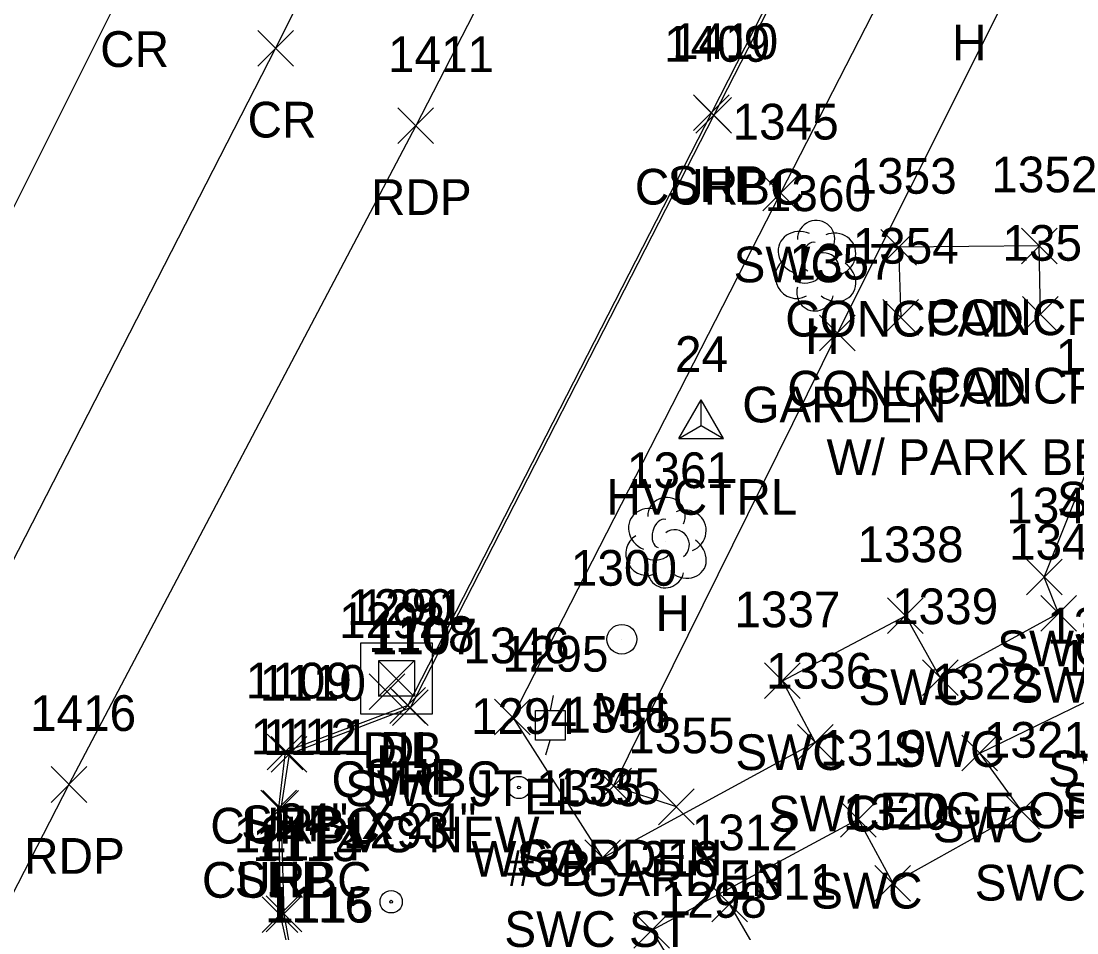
# Model space of a CAD drawing. Extents: x 1462668 to 1465147, y 550359 to 557351.
# Drawn here: x 1464628.9 to 1464688, y 552499.8 to 552550.9 of the extents above; entities that cross this region are included whole.
import ezdxf

# ---------------------------------------------------------------- set-up
doc = ezdxf.new("R2010")
doc.units = 0
for name, color, linetype in [('C_A', 7, 'Continuous'), ('C_I', 7, 'Continuous'), ('CPSM', 7, 'Continuous'), ('D_A', 7, 'Continuous'), ('D_C', 7, 'Continuous'), ('D_I', 7, 'Continuous'), ('D_TIC', 7, 'Continuous'), ('DS', 7, 'Continuous'), ('L_A', 7, 'Continuous'), ('L_C', 7, 'Continuous'), ('L_I', 7, 'Continuous'), ('L_TIC', 7, 'Continuous'), ('LAPB', 7, 'Continuous'), ('LS', 7, 'Continuous'), ('LTD', 7, 'Continuous'), ('P_A', 7, 'Continuous'), ('P_I', 7, 'Continuous'), ('P_TIC', 7, 'Continuous'), ('PET', 7, 'Continuous'), ('PRC', 7, 'Continuous'), ('PSP', 7, 'Continuous'), ('R_A', 7, 'Continuous'), ('R_C', 7, 'Continuous'), ('R_I', 7, 'Continuous'), ('R_TIC', 7, 'Continuous'), ('RC', 7, 'Continuous'), ('RSW', 7, 'Continuous'), ('U_A', 7, 'Continuous'), ('U_C', 7, 'Continuous'), ('U_I', 7, 'Continuous'), ('UEPT', 7, 'Continuous'), ('UUMH', 7, 'Continuous'), ('UWV', 7, 'Continuous')]:
    doc.layers.add(name, color=color, linetype=linetype)

msp = doc.modelspace()

# ---------------------------------------------------------------- linework, layer by layer
at = {"layer": 'CPSM'}
for p, q in [((1464665.713, 552527.513), (1464666.963, 552529.678)), ((1464668.213, 552527.513), (1464666.963, 552529.678)), ((1464666.964, 552528.235), (1464666.963, 552529.678)), ((1464665.713, 552527.513), (1464666.964, 552528.235)), ((1464666.964, 552528.235), (1464666.964, 552528.235)), ((1464666.964, 552528.235), (1464668.213, 552527.513)), ((1464665.713, 552527.513), (1464668.213, 552527.513))]:
    msp.add_line(p, q, dxfattribs=at)
at = {"layer": 'D_TIC'}
for points in [[(1464648.888, 552513.055), (1464650.888, 552515.055)], [(1464650.888, 552513.055), (1464648.888, 552515.055)], [(1464648.362, 552512.327), (1464650.362, 552514.327)], [(1464650.362, 552512.327), (1464648.362, 552514.327)]]:
    msp.add_lwpolyline(points, dxfattribs=at)
at = {"layer": 'DS'}
for p, q in [((1464647.898, 552516.066), (1464651.898, 552516.066)), ((1464647.898, 552512.066), (1464647.898, 552516.066)), ((1464651.898, 552516.066), (1464651.898, 552512.066)), ((1464648.898, 552513.066), (1464648.898, 552515.066)), ((1464648.898, 552515.066), (1464650.898, 552515.066)), ((1464650.898, 552515.066), (1464650.898, 552513.066)), ((1464649.903, 552514.067), (1464649.903, 552514.067)), ((1464649.903, 552514.067), (1464649.903, 552514.067)), ((1464650.898, 552513.066), (1464648.898, 552513.066)), ((1464651.898, 552512.066), (1464647.898, 552512.066))]:
    msp.add_line(p, q, dxfattribs=at)
at = {"layer": 'L_TIC'}
for points in [[(1464677.031, 552537.217), (1464679.031, 552539.217)], [(1464679.031, 552537.217), (1464677.031, 552539.217)], [(1464684.916, 552537.295), (1464686.916, 552539.295)], [(1464686.916, 552537.295), (1464684.916, 552539.295)], [(1464677.147, 552533.299), (1464679.147, 552535.299)], [(1464679.147, 552533.299), (1464677.147, 552535.299)], [(1464684.975, 552533.463), (1464686.975, 552535.463)], [(1464686.975, 552533.463), (1464684.975, 552535.463)], [(1464673.601, 552532.409), (1464675.601, 552534.409)], [(1464675.601, 552532.409), (1464673.601, 552534.409)], [(1464661.053, 552507.037), (1464663.053, 552509.037)], [(1464663.053, 552507.037), (1464661.053, 552509.037)], [(1464664.574, 552505.875), (1464666.574, 552507.875)], [(1464666.574, 552505.875), (1464664.574, 552507.875)], [(1464667.56, 552500.44), (1464669.56, 552502.44)], [(1464669.56, 552500.44), (1464667.56, 552502.44)]]:
    msp.add_lwpolyline(points, dxfattribs=at)
at = {"layer": 'LAPB'}
for points in [[(1464665.574, 552506.875), (1464662.053, 552508.037), (1464674.601, 552533.409), (1464686.617, 552557.372)], [(1464718.311, 552483.565), (1464695.5, 552491.204), (1464670.152, 552498.676), (1464668.56, 552501.44)]]:
    msp.add_lwpolyline(points, dxfattribs=at)
at = {"layer": 'LS'}
msp.add_line((1464678.147, 552534.299), (1464678.147, 552534.299), dxfattribs=at)
msp.add_lwpolyline([(1464685.975, 552534.463), (1464685.916, 552538.295), (1464678.031, 552538.217), (1464678.147, 552534.299)], dxfattribs=at)
at = {"layer": 'LTD'}
for p, q in [((1464673.36, 552537.241), (1464673.36, 552537.241)), ((1464673.36, 552537.241), (1464673.36, 552537.241)), ((1464664.976, 552521.729), (1464664.976, 552521.729)), ((1464664.976, 552521.729), (1464664.976, 552521.729))]:
    msp.add_line(p, q, dxfattribs=at)
for centre in [(1464673.407, 552538.675), (1464665.023, 552523.163)]:
    msp.add_arc(centre, 1.047, 335.52715, 180.95627, dxfattribs=at)
for centre, major_axis, ratio, start_param, end_param in [((1464672.569, 552537.907), (1.21, -0.512), 0.895232, 1.570796, 4.712389), ((1464674.402, 552537.824), (-1.141, -0.483), 0.949671, 1.570796, 4.712389), ((1464673.152, 552537.699), (-0.208, -0.792), 0.645439, 3.141593, 6.283185), ((1464672.277, 552536.532), (0.584, -1.042), 0.959034, 3.141593, 6.283185), ((1464673.86, 552537.074), (-0.5, 0.667), 0.989748, 3.141593, 6.283185), ((1464674.361, 552536.408), (-1.09, 0.792), 0.841452, 1.570796, 4.712389), ((1464672.902, 552536.491), (-0.625, -0.083), 0.423636, 0, 3.141593), ((1464673.361, 552535.741), (0.265, 1.061), 0.942809, 1.570796, 4.712389), ((1464664.184, 552522.395), (1.21, -0.512), 0.895232, 1.570796, 4.712389), ((1464666.018, 552522.312), (-1.141, -0.483), 0.949671, 1.570796, 4.712389), ((1464664.768, 552522.187), (-0.208, -0.792), 0.645439, 3.141593, 6.283185), ((1464665.476, 552521.562), (-0.5, 0.667), 0.989748, 3.141593, 6.283185), ((1464663.893, 552521.02), (0.584, -1.042), 0.959034, 3.141593, 6.283185), ((1464665.976, 552520.896), (-1.09, 0.792), 0.841452, 1.570796, 4.712389), ((1464664.518, 552520.979), (-0.625, -0.083), 0.423636, 0, 3.141593), ((1464664.976, 552520.229), (0.265, 1.061), 0.942809, 1.570796, 4.712389)]:
    msp.add_ellipse(centre, major_axis=major_axis, ratio=ratio, start_param=start_param, end_param=end_param, dxfattribs=at)
at = {"layer": 'P_TIC'}
for points in [[(1464642.112, 552548.366), (1464644.112, 552550.366)], [(1464644.112, 552548.366), (1464642.112, 552550.366)], [(1464666.542, 552544.757), (1464668.542, 552546.757)], [(1464668.542, 552544.757), (1464666.542, 552546.757)], [(1464649.971, 552544.028), (1464651.971, 552546.028)], [(1464651.971, 552544.028), (1464649.971, 552546.028)], [(1464649.522, 552511.551), (1464651.522, 552513.551)], [(1464651.522, 552511.551), (1464649.522, 552513.551)], [(1464642.648, 552508.949), (1464644.648, 552510.949)], [(1464644.648, 552508.949), (1464642.648, 552510.949)], [(1464630.533, 552507.126), (1464632.533, 552509.126)], [(1464632.533, 552507.126), (1464630.533, 552509.126)], [(1464642.288, 552505.811), (1464644.288, 552507.811)], [(1464644.288, 552505.811), (1464642.288, 552507.811)], [(1464642.368, 552499.834), (1464644.368, 552501.834)], [(1464644.368, 552499.834), (1464642.368, 552501.834)]]:
    msp.add_lwpolyline(points, dxfattribs=at)
at = {"layer": 'PET'}
msp.add_lwpolyline([(1464688.812, 552609.874), (1464680.611, 552601.191), (1464673.858, 552589.463), (1464650.971, 552545.028), (1464631.533, 552508.126), (1464616.104, 552478.119), (1464603.71, 552453.411)], dxfattribs=at)
at = {"layer": 'PRC'}
for points in [[(1464682.067, 552623.831), (1464670.226, 552603.072), (1464657.19, 552577.372), (1464643.112, 552549.366), (1464624.394, 552512.893)], [(1464665.112, 552617.199), (1464647.939, 552582.04), (1464634.853, 552553.318), (1464610.757, 552505.159), (1464598.841, 552479.239), (1464581.961, 552444.147)]]:
    msp.add_lwpolyline(points, dxfattribs=at)
at = {"layer": 'PSP'}
for points in [[(1464681.439, 552581.987), (1464681.093, 552572.305), (1464667.542, 552545.757)], [(1464667.542, 552545.757), (1464650.522, 552512.551)], [(1464650.522, 552512.551), (1464643.648, 552509.949), (1464643.288, 552506.811), (1464643.368, 552500.834), (1464644.133, 552497.411), (1464645.397, 552494.053), (1464648.672, 552490.102), (1464652.246, 552487.443), (1464656.969, 552484.6), (1464662.34, 552487.953), (1464696.464, 552477.877), (1464733.473, 552466.932), (1464744.351, 552464.746), (1464754.99, 552461.434)]]:
    msp.add_lwpolyline(points, dxfattribs=at)
at = {"layer": 'R_TIC'}
for points in [[(1464666.666, 552544.609), (1464668.666, 552546.609)], [(1464668.666, 552544.609), (1464666.666, 552546.609)], [(1464670.418, 552540.254), (1464672.418, 552542.254)], [(1464672.418, 552540.254), (1464670.418, 552542.254)], [(1464685.189, 552518.749), (1464687.189, 552520.749)], [(1464687.189, 552518.749), (1464685.189, 552520.749)], [(1464685.995, 552516.716), (1464687.995, 552518.716)], [(1464687.995, 552516.716), (1464685.995, 552518.716)], [(1464677.412, 552516.58), (1464679.412, 552518.58)], [(1464679.412, 552516.58), (1464677.412, 552518.58)], [(1464679.362, 552513.108), (1464681.362, 552515.108)], [(1464681.362, 552513.108), (1464679.362, 552515.108)], [(1464670.518, 552512.936), (1464672.518, 552514.936)], [(1464672.518, 552512.936), (1464670.518, 552514.936)], [(1464649.664, 552511.422), (1464651.664, 552513.422)], [(1464651.664, 552511.422), (1464649.664, 552513.422)], [(1464655.387, 552510.914), (1464657.387, 552512.914)], [(1464657.387, 552510.914), (1464655.387, 552512.914)], [(1464672.357, 552509.494), (1464674.357, 552511.494)], [(1464674.357, 552509.494), (1464672.357, 552511.494)], [(1464642.873, 552508.82), (1464644.873, 552510.82)], [(1464644.873, 552508.82), (1464642.873, 552510.82)], [(1464681.577, 552508.889), (1464683.577, 552510.889)], [(1464683.577, 552508.889), (1464681.577, 552510.889)], [(1464642.404, 552505.783), (1464644.404, 552507.783)], [(1464644.404, 552505.783), (1464642.404, 552507.783)], [(1464683.928, 552505.628), (1464685.928, 552507.628)], [(1464685.928, 552505.628), (1464683.928, 552507.628)], [(1464674.769, 552505.179), (1464676.769, 552507.179)], [(1464676.769, 552505.179), (1464674.769, 552507.179)], [(1464660.438, 552503.028), (1464662.438, 552505.028)], [(1464662.438, 552503.028), (1464660.438, 552505.028)], [(1464676.7, 552501.593), (1464678.7, 552503.593)], [(1464678.7, 552501.593), (1464676.7, 552503.593)], [(1464642.586, 552499.881), (1464644.586, 552501.881)], [(1464644.586, 552499.881), (1464642.586, 552501.881)], [(1464663.195, 552498.959), (1464665.195, 552500.959)], [(1464665.195, 552498.959), (1464663.195, 552500.959)]]:
    msp.add_lwpolyline(points, dxfattribs=at)
at = {"layer": 'RC'}
for points in [[(1464681.722, 552581.93), (1464681.339, 552572.255), (1464667.666, 552545.609)], [(1464667.666, 552545.609), (1464650.664, 552512.422)], [(1464650.664, 552512.422), (1464643.873, 552509.82), (1464643.404, 552506.783), (1464643.586, 552500.881), (1464644.198, 552497.394), (1464645.612, 552494.161), (1464648.838, 552490.193), (1464652.357, 552487.667), (1464656.847, 552484.922), (1464662.253, 552488.189), (1464696.305, 552478.146), (1464733.624, 552467.159), (1464744.218, 552465.259), (1464754.798, 552461.811)]]:
    msp.add_lwpolyline(points, dxfattribs=at)
at = {"layer": 'RSW'}
for points in [[(1464661.438, 552504.028), (1464673.357, 552510.494), (1464671.518, 552513.936), (1464678.412, 552517.58), (1464680.362, 552514.108), (1464686.995, 552517.716), (1464686.189, 552519.749), (1464689.538, 552528.083), (1464698.222, 552531.926), (1464683.825, 552565.46), (1464671.418, 552541.254), (1464656.387, 552511.914)], [(1464728.045, 552474.346), (1464722.059, 552476.092), (1464695.994, 552483.871), (1464669.102, 552491.976), (1464664.195, 552499.959), (1464675.769, 552506.179), (1464677.7, 552502.593), (1464684.928, 552506.628), (1464682.577, 552509.889), (1464689.047, 552513.023), (1464689.809, 552511.219), (1464698.36, 552507.497), (1464707.199, 552511.162)], [(1464656.387, 552511.914), (1464661.438, 552504.028)]]:
    msp.add_lwpolyline(points, dxfattribs=at)
at = {"layer": 'UEPT'}
for p, q in [((1464658.679, 552513.113), (1464658.512, 552512.28)), ((1464657.679, 552510.613), (1464657.679, 552512.28)), ((1464657.679, 552512.28), (1464659.346, 552512.28)), ((1464659.346, 552512.28), (1464659.346, 552510.613)), ((1464658.512, 552511.447), (1464658.512, 552511.447)), ((1464659.346, 552510.613), (1464657.679, 552510.613)), ((1464658.262, 552509.78), (1464658.512, 552510.613))]:
    msp.add_line(p, q, dxfattribs=at)
at = {"layer": 'UUMH'}
for p, q in [((1464662.521, 552516.26), (1464662.521, 552516.26)), ((1464663.355, 552516.26), (1464663.355, 552516.26))]:
    msp.add_line(p, q, dxfattribs=at)
msp.add_circle((1464662.521, 552516.26), 0.833, dxfattribs=at)
at = {"layer": 'UWV'}
for centre, radius in [((1464656.755, 552507.958), 0.625), ((1464656.755, 552507.958), 0.0833), ((1464649.593, 552501.556), 0.625), ((1464649.593, 552501.556), 0.0833)]:
    msp.add_circle(centre, radius, dxfattribs=at)

# ---------------------------------------------------------------- texts
at = {"layer": 'C_A'}
msp.add_text('HVCTRL', height=2, dxfattribs=at).set_placement((1464661.657, 552523.235))
at = {"layer": 'C_I'}
msp.add_text('24', height=2, dxfattribs=at).set_placement((1464665.499, 552531.235))
at = {"layer": 'D_A'}
for s, p in [('DIB', (1464647.99, 552509.055)), ('DI', (1464648.958, 552509.067)), ('P', (1464648.74, 552508.327))]:
    msp.add_text(s, height=2, dxfattribs=at).set_placement(p)
at = {"layer": 'D_C'}
for s, p in [('24" X 24"', (1464643.257, 552505.067)), ('12" PVC NEW', (1464640.764, 552504.327))]:
    msp.add_text(s, height=2, dxfattribs=at).set_placement(p)
at = {"layer": 'D_I'}
for s, p in [('1290', (1464647.124, 552517.067)), ('1291', (1464647.762, 552517.055)), ('1292', (1464646.669, 552516.327))]:
    msp.add_text(s, height=2, dxfattribs=at).set_placement(p)
at = {"layer": 'L_A'}
for s, p in [('H', (1464681.029, 552548.683)), ('CONCPAD', (1464671.676, 552533.217)), ('CONCPAD', (1464679.562, 552533.295)), ('H', (1464672.793, 552532.241)), ('CONCPAD', (1464671.793, 552529.299)), ('CONCPAD', (1464679.621, 552529.463)), ('GARDEN', (1464669.27, 552528.409)), ('H', (1464664.409, 552516.729)), ('GARDEN', (1464656.723, 552503.037)), ('GARDEN', (1464660.243, 552501.875))]:
    msp.add_text(s, height=2, dxfattribs=at).set_placement(p)
at = {"layer": 'L_C'}
msp.add_text('W/ PARK BENCH', height=2, dxfattribs=at).set_placement((1464673.991, 552525.463))
at = {"layer": 'L_I'}
for s, p in [('1353', (1464675.338, 552541.217)), ('1352', (1464683.223, 552541.295)), ('1360', (1464670.534, 552540.241)), ('1354', (1464675.454, 552537.299)), ('1351', (1464683.849, 552537.463)), ('1357', (1464671.908, 552536.409)), ('1361', (1464662.803, 552524.729)), ('1356', (1464659.305, 552511.037)), ('1355', (1464662.881, 552509.875)), ('1312', (1464666.434, 552504.44)), ('1311', (1464668.593, 552501.676))]:
    msp.add_text(s, height=2, dxfattribs=at).set_placement(p)
at = {"layer": 'P_A'}
for s, p in [('CR', (1464633.286, 552548.318)), ('CR', (1464641.545, 552544.366)), ('SHP', (1464665.077, 552540.757)), ('RDP', (1464648.459, 552540.028)), ('SHP', (1464648.058, 552507.551)), ('SHP', (1464641.184, 552504.949)), ('RDP', (1464629.021, 552503.126)), ('SHP', (1464640.823, 552501.811))]:
    msp.add_text(s, height=2, dxfattribs=at).set_placement(p)
at = {"layer": 'P_I'}
for s, p in [('1410', (1464665.329, 552548.757)), ('1411', (1464649.412, 552548.028)), ('1108', (1464648.317, 552515.551)), ('1109', (1464641.436, 552512.949)), ('1416', (1464629.352, 552511.126)), ('1112', (1464641.729, 552509.811)), ('1113', (1464641.809, 552503.834)), ('1116', (1464642.519, 552500.411))]:
    msp.add_text(s, height=2, dxfattribs=at).set_placement(p)
at = {"layer": 'R_A'}
for s, p in [('CURBC', (1464663.248, 552540.609)), ('SWC', (1464668.78, 552536.254)), ('SWC', (1464686.9, 552523.083)), ('SWC', (1464683.552, 552514.749)), ('SWC', (1464675.775, 552512.58)), ('SWC', (1464684.357, 552512.716)), ('SWC', (1464668.88, 552508.936)), ('SWC', (1464677.724, 552509.108)), ('SWC', (1464686.409, 552508.023)), ('CURBC', (1464646.246, 552507.422)), ('SWC JT 1335', (1464647.017, 552506.914)), ('SWC', (1464687.171, 552506.219)), ('SWC', (1464670.719, 552505.494)), ('CURBC', (1464639.456, 552504.82)), ('SWC', (1464679.939, 552504.889)), ('CURBC', (1464638.987, 552501.783)), ('SWC', (1464682.291, 552501.628)), ('SWC', (1464673.131, 552501.179)), ('SWC ST', (1464655.934, 552499.028))]:
    msp.add_text(s, height=2, dxfattribs=at).set_placement(p)
at = {"layer": 'R_C'}
msp.add_text('EDGE OF MARBLE WATER FOUNTAIN', height=2, dxfattribs=at).set_placement((1464676.961, 552505.676))
at = {"layer": 'R_I'}
for s, p in [('1409', (1464664.886, 552548.609)), ('1345', (1464668.725, 552544.254)), ('1342', (1464686.845, 552531.083)), ('1341', (1464684.063, 552522.749)), ('1338', (1464675.72, 552520.58)), ('1340', (1464684.215, 552520.716)), ('1337', (1464668.825, 552516.936)), ('1339', (1464677.661, 552517.108)), ('1323', (1464686.354, 552516.023)), ('1107', (1464648.459, 552515.422)), ('1346', (1464653.639, 552514.914)), ('1324', (1464687.116, 552514.219)), ('1336', (1464670.609, 552513.494)), ('1110', (1464642.228, 552512.82)), ('1322', (1464679.884, 552512.889)), ('1111', (1464642.412, 552509.783)), ('1321', (1464682.802, 552509.628)), ('1319', (1464673.635, 552509.179)), ('1335', (1464658.745, 552507.028)), ('1320', (1464674.921, 552505.593)), ('1114', (1464642.027, 552503.881)), ('1318', (1464662.069, 552502.959)), ('1115', (1464642.639, 552500.394))]:
    msp.add_text(s, height=2, dxfattribs=at).set_placement(p)
at = {"layer": 'U_A'}
for s, p in [('MH', (1464660.884, 552511.26)), ('EL', (1464657.048, 552506.447)), ('WSO', (1464654.086, 552502.958))]:
    msp.add_text(s, height=2, dxfattribs=at).set_placement(p)
at = {"layer": 'U_C'}
msp.add_text('#3B', height=2, dxfattribs=at).set_placement((1464656.095, 552502.447))
at = {"layer": 'U_I'}
for s, p in [('1300', (1464659.663, 552519.26)), ('1295', (1464655.82, 552514.447)), ('1294', (1464654.062, 552510.958)), ('1293', (1464646.9, 552504.556)), ('1298', (1464664.693, 552500.662))]:
    msp.add_text(s, height=2, dxfattribs=at).set_placement(p)

doc.saveas('drawing.dxf')
